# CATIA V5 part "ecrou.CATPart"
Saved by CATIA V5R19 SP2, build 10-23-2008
Part number: ecrou1
Nomenclature: 5
Bounding box of the stored display mesh (mm): x 0 to 8.4, y -9.364 to 9.084, z -8.158 to 8
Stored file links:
  D:\SCHOOL\FRANCE\BANC_POUTRE_EN_MOUSSE\ecrou.CATPart
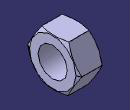
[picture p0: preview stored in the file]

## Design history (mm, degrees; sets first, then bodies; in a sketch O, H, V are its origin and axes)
Body1 (main body)
  Sketch1 on yz-plane, origin (0, 0, 0), H (0, 1, 0), V (0, 0, 1)
    circle A1 centre (0, 0) radius 9.225
    radius A1 = 9.225
  Pad1: profile Sketch1, direction (1, 0, 0), length 8.4
  Chamfer1: length 1.3, angle 30, on edge [face of Pad1 | face of Pad1]
  Chamfer2: length 1.3, angle 30, on edge [face of Pad1 | face of Pad1]
  Body2
    Sketch2 on face of Pad1, origin (8.4, 0, 0), H (0, 1, 0), V (0, 0, 1)
      point P1 (4.6188, -8)
      point P2 (9.2376, 0)
      point P3 (4.6188, 8)
      point P4 (-4.6188, 8)
      point P5 (-9.2376, 0)
      point P6 (-4.6188, -8)
      point P7 (6.9282, -4)
      line L1 (4.6188, -8) -> (9.2376, 0)
      line L2 (9.2376, 0) -> (4.6188, 8)
      line L3 (4.6188, 8) -> (-4.6188, 8)
      line L4 (-4.6188, 8) -> (-9.2376, 0)
      line L5 (-9.2376, 0) -> (-4.6188, -8)
      line L6 (-4.6188, -8) -> (4.6188, -8)
      construction line L7 (0, 0) -> (6.9282, -4)
      construction circle A1 centre (0, 0) radius 9.2376
      construction arc A2 centre (-9.2376, 0) radius 9.2376 from (-4.6188, 8) to (-4.6188, -8) cw
      construction arc A3 centre (9.2376, 0) radius 9.2376 from (4.6188, 8) to (4.6188, -8) ccw
      length L7 = 8
      coincidence: A1 P1, A1 P2, A1 P3, A1 P4, A1 P5, A1 P6, A2 O, A3 O
      midpoint: P7 L1
      parallelism: L1 L4
      horizontal: L3 H
    Pad2: profile Sketch2, direction (-1, 0, 0), length 8.4
  Intersect1: tool Body2
  Sketch3 on face of Pad1, origin (8.4, -0.4473, 0.4844), H (0, 1, 0), V (0, 0, 1)
    point P1 (0.4473, -0.4844)
    reference projected circle E1 centre (0.4473, -0.4844) radius 7.925 from edge of Chamfer1
    concentricity: E1 P1
  Hole1: placed by Sketch3, at (8.4, 0, 0) direction (-1, 0, 0), diameter 10, through (limit type 6)
  Rotate1: ToTransfor Hole1, Axis edge [face of Pad1 | face of Pad2], Angle 10
  Rotate2: ToTransfor Rotate1, Axis edge [face of Pad1 | face of Pad2], Angle 351
  Sketch4 on face of Rotate2, origin (8.4, 0, 0), H (0, 1, 0), V (0, 0, 1)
